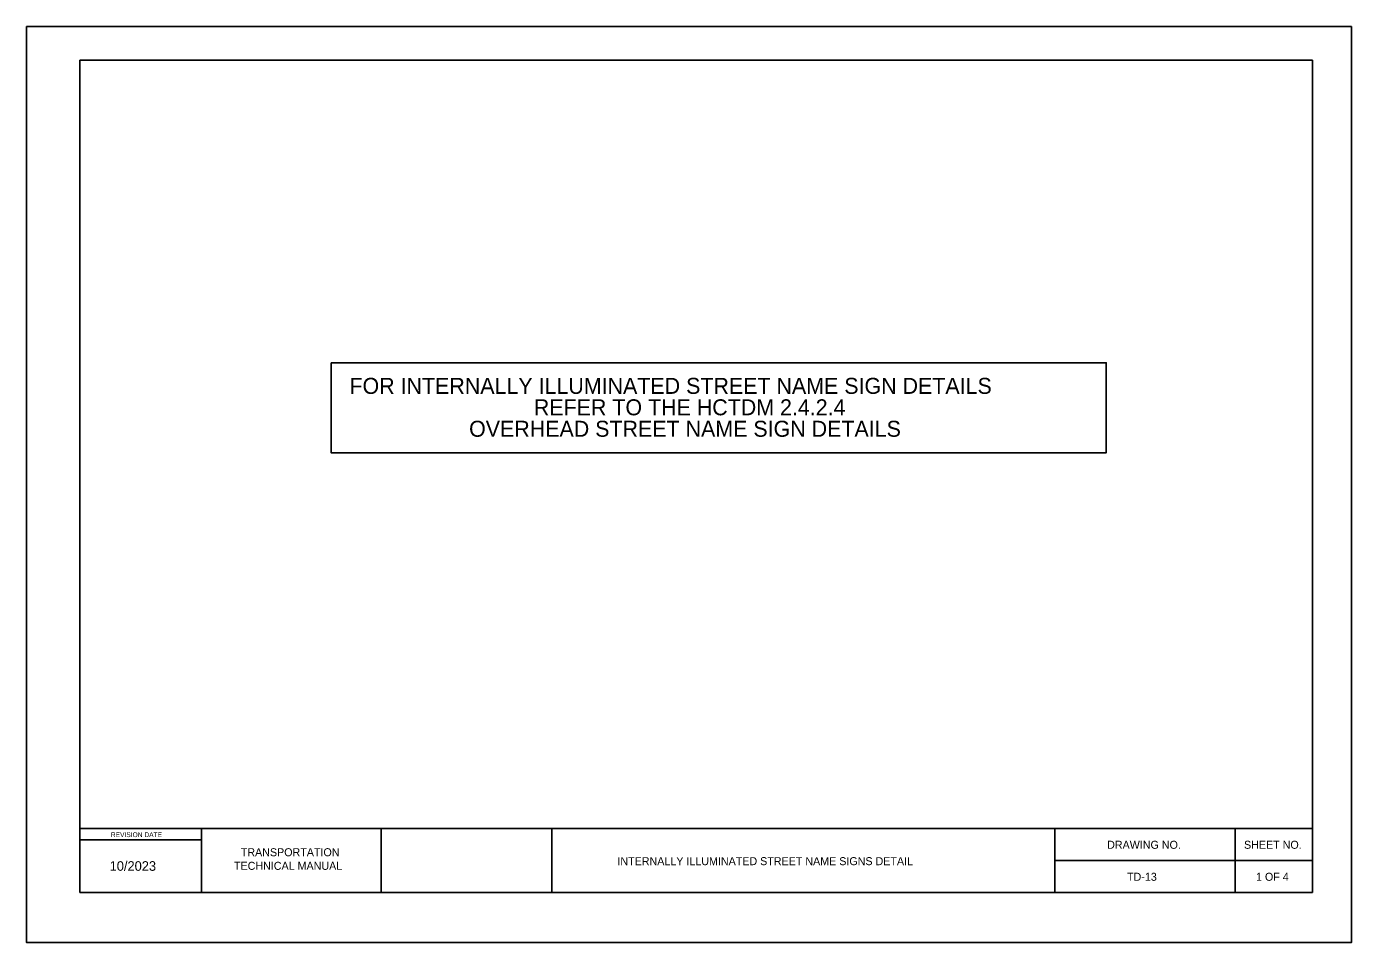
# Model space of a CAD drawing. Extents: x -14.6 to 39.7, y -12.4 to 25.1.
import ezdxf

# ---------------------------------------------------------------- set-up
doc = ezdxf.new("R2010")
doc.units = 0
for name, color, linetype in [('Default', 7, 'Continuous'), ('NonPlottingEle_dp', 7, 'Continuous'), ('SheetBorder_dp', 7, 'Continuous'), ('SheetLines_dp', 7, 'Continuous'), ('TextMinor', 7, 'Continuous')]:
    doc.layers.add(name, color=color, linetype=linetype)

msp = doc.modelspace()

# ---------------------------------------------------------------- linework, layer by layer
at = {"layer": 'Default'}
msp.add_lwpolyline([(-2.085, 11.359), (29.691, 11.359), (29.691, 7.669), (-2.085, 7.669)], close=True, dxfattribs=at)
at = {"layer": 'NonPlottingEle_dp'}
msp.add_lwpolyline([(38.12, 25.141), (-14.569, 25.141), (-14.569, -12.409), (39.74, -12.409), (39.74, 25.141)], close=True, dxfattribs=at)
at = {"layer": 'SheetBorder_dp'}
for p, q in [((-12.382, 23.76), (-12.382, -10.361)), ((-12.382, 23.76), (38.143, 23.76)), ((38.143, 23.76), (38.143, -10.361)), ((-12.382, -7.741), (38.143, -7.741)), ((-12.382, -10.361), (38.143, -10.361))]:
    msp.add_line(p, q, dxfattribs=at)
at = {"layer": 'SheetLines_dp'}
for p, q in [((-7.394, -7.736), (-7.394, -10.361)), ((-0.027, -7.736), (-0.027, -10.361)), ((6.968, -7.741), (6.968, -10.361)), ((27.582, -10.361), (27.582, -7.736)), ((34.972, -10.361), (34.972, -7.736)), ((-12.382, -8.196), (-7.394, -8.196)), ((27.582, -9.049), (38.143, -9.049))]:
    msp.add_line(p, q, dxfattribs=at)

# ---------------------------------------------------------------- texts
at = {"layer": 'TextMinor'}
for s, height, p in [('FOR INTERNALLY ILLUMINATED STREET NAME SIGN DETAILS ', 0.65617, (-1.332, 10.082)), ('REFER TO THE HCTDM 2.4.2.4 ', 0.65617, (6.226, 9.203)), ('OVERHEAD STREET NAME SIGN DETAILS', 0.65617, (3.572, 8.323)), ('REVISION DATE', 0.19685, (-11.112, -8.089)), ('TRANSPORTATION', 0.32808, (-5.786, -8.873)), ('DRAWING NO.', 0.32808, (29.724, -8.567)), ('SHEET NO.', 0.3281, (35.335, -8.567)), ('10/2023', 0.3937, (-11.162, -9.47)), ('TECHNICAL MANUAL', 0.32808, (-6.066, -9.43)), ('INTERNALLY ILLUMINATED STREET NAME SIGNS DETAIL', 0.32808, (9.651, -9.239)), ('TD-13', 0.3281, (30.541, -9.879)), ('1 OF 4 ', 0.3281, (35.827, -9.879))]:
    msp.add_text(s, height=height, dxfattribs=at).set_placement(p)

doc.saveas('drawing.dxf')
